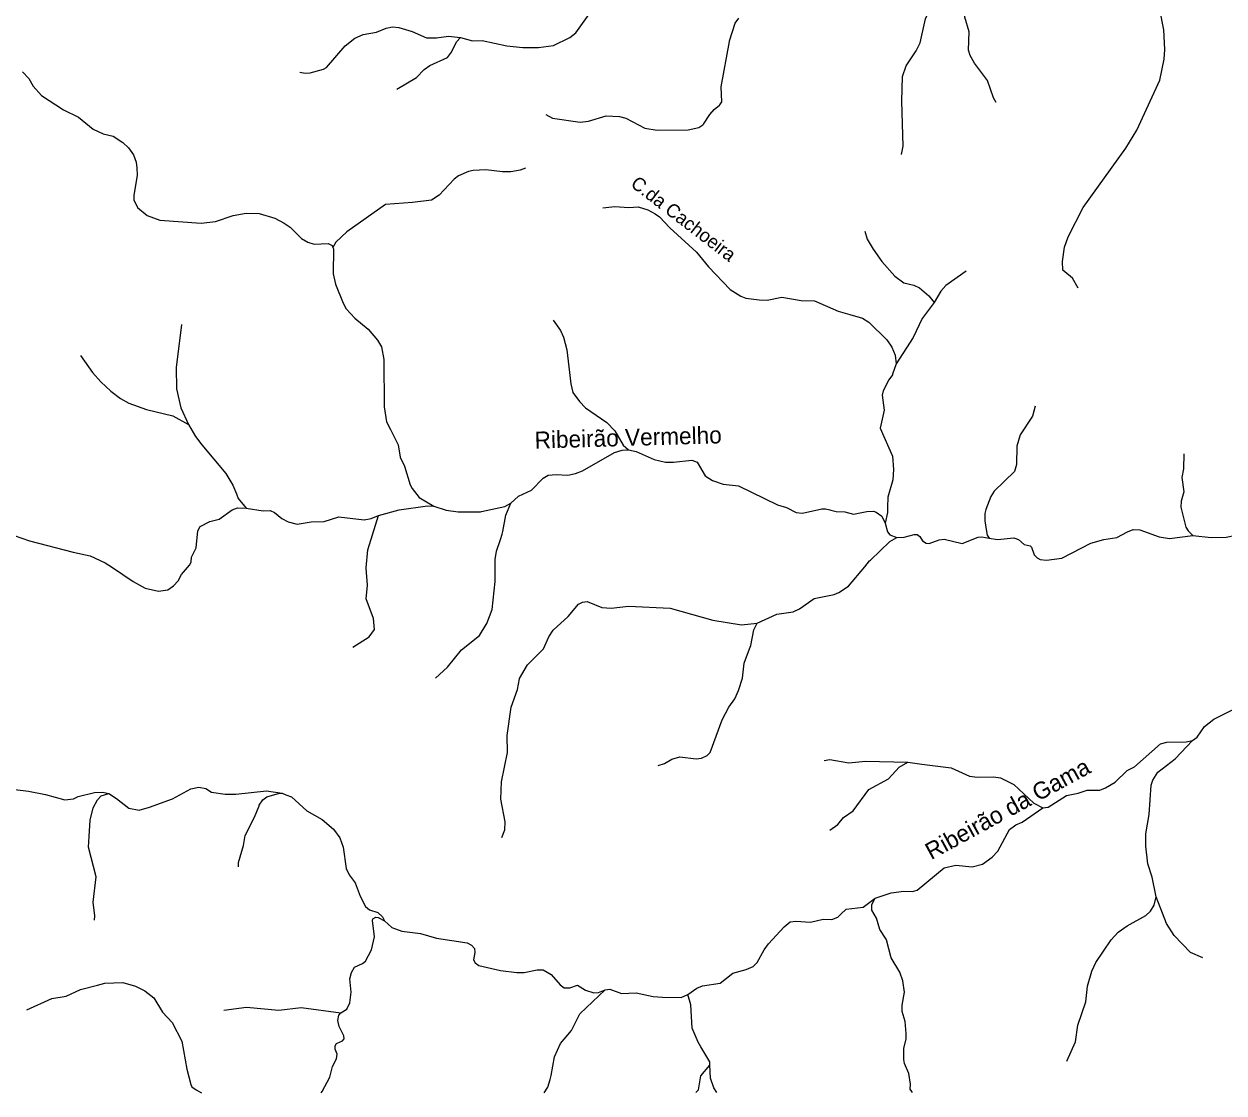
# Model space of a CAD drawing. Extents: x 473.9 to 500, y 7733.1 to 7760.8.
# Drawn here: x 487.45 to 494.55, y 7733.15 to 7739.47 of the extents above; entities that cross this region are included whole.
import ezdxf
from ezdxf.enums import TextEntityAlignment as Align

# ---------------------------------------------------------------- set-up
doc = ezdxf.new("R2010")
doc.units = 0
doc.header["$LTSCALE"] = 0.032
doc.layers.add('61', color=7, linetype='Continuous')
doc.layers.add('7', color=7, linetype='Continuous', lineweight=25)

msp = doc.modelspace()

# ---------------------------------------------------------------- linework, layer by layer
at = {"layer": '7'}
for points in [[(493.6912, 7737.9093), (493.6577, 7737.9688), (493.6116, 7738.0062), (493.6003, 7738.0154), (493.5974, 7738.0668), (493.61, 7738.1504), (493.6319, 7738.2133), (493.7196, 7738.3864), (493.9716, 7738.7369), (494.0376, 7738.8435), (494.0496, 7738.8696), (494.1733, 7739.1388), (494.2, 7739.2633), (494.2032, 7739.3203), (494.1976, 7739.4368), (494.1743, 7739.557), (494.1743, 7739.5915), (494.1743, 7739.6289), (494.2017, 7739.7973), (494.222, 7739.8595), (494.2343, 7739.8973), (494.2556, 7739.9383)], [(490.0364, 7739.3905), (490.1076, 7739.3721), (490.1641, 7739.3732), (490.3094, 7739.3429), (490.4052, 7739.3316), (490.4964, 7739.3316), (490.5852, 7739.3443), (490.6836, 7739.3919), (490.7178, 7739.4189), (490.8371, 7739.5847), (490.9115, 7739.6731), (490.9589, 7739.7258), (491.038, 7739.7976), (491.0653, 7739.8128), (491.084, 7739.815)], [(490.5407, 7738.9368), (490.5796, 7738.9151), (490.7432, 7738.8907), (490.7926, 7738.8955), (490.8972, 7738.9275), (490.9755, 7738.9242), (491.0139, 7738.9137), (491.1269, 7738.8556), (491.1986, 7738.8426), (491.3834, 7738.845), (491.4457, 7738.8589), (491.4689, 7738.8746), (491.4744, 7738.8783), (491.5119, 7738.936), (491.5369, 7738.9664), (491.5691, 7738.9915), (491.5702, 7738.9933), (491.5812, 7739.0106), (491.5782, 7739.0996), (491.6273, 7739.3685), (491.628, 7739.3723), (491.6613, 7739.4769), (491.683, 7739.5064)], [(492.6452, 7738.6987), (492.6541, 7738.7489), (492.6469, 7739.0153), (492.651, 7739.1606), (492.6735, 7739.2246), (492.7318, 7739.3132), (492.7545, 7739.3588), (492.7874, 7739.5024), (492.8039, 7739.5382)], [(493.2053, 7739.0062), (493.1897, 7739.0345), (493.154, 7739.1369), (493.0778, 7739.2391), (493.0515, 7739.2841), (493.0422, 7739.3172), (493.0462, 7739.4255), (493.0198, 7739.5121), (493.02, 7739.529), (493.037, 7739.5535)], [(489.086, 7739.1867), (489.1167, 7739.18), (489.1462, 7739.1825), (489.2253, 7739.2031), (489.2438, 7739.2142), (489.3537, 7739.3418), (489.4096, 7739.3866), (489.4597, 7739.4098), (489.5386, 7739.4222), (489.5956, 7739.4466), (489.6327, 7739.4542), (489.6701, 7739.451), (489.7494, 7739.4257), (489.8338, 7739.3889), (489.893, 7739.3894), (489.9643, 7739.3989), (490.0364, 7739.3905)], [(489.6591, 7739.0864), (489.7745, 7739.1544), (489.8204, 7739.2023), (489.8537, 7739.2259), (489.9582, 7739.2726), (489.9833, 7739.3036), (490.0116, 7739.3651), (490.0364, 7739.3905)], [(487.4447, 7739.1879), (487.482, 7739.1485), (487.5073, 7739.1041), (487.5573, 7739.0482), (487.6865, 7738.9634), (487.7754, 7738.9206), (487.8629, 7738.8483), (487.9214, 7738.8219), (487.98, 7738.8079), (488.0372, 7738.7697), (488.0706, 7738.7396), (488.1006, 7738.6968), (488.1161, 7738.6545), (488.1209, 7738.6209), (488.1217, 7738.5767), (488.1028, 7738.4565), (488.1038, 7738.4315), (488.1241, 7738.3865), (488.181, 7738.3392), (488.2567, 7738.3115), (488.5019, 7738.294), (488.5864, 7738.3035), (488.6908, 7738.3383), (488.7679, 7738.3533), (488.8447, 7738.3501), (488.9373, 7738.3228), (488.9929, 7738.2934), (489.027, 7738.2692), (489.0958, 7738.2034), (489.1321, 7738.1813), (489.1697, 7738.1694), (489.2526, 7738.1722), (489.2759, 7738.1603), (489.2809, 7738.1501)], [(490.4204, 7738.6182), (490.3878, 7738.606), (490.3332, 7738.5964), (490.2837, 7738.5964), (490.1854, 7738.6092), (490.1115, 7738.6052), (490.0822, 7738.598), (490.0248, 7738.5734), (489.9981, 7738.5534), (489.9096, 7738.4592), (489.8634, 7738.4299), (489.7521, 7738.4155), (489.5927, 7738.4046), (489.3634, 7738.2411), (489.2983, 7738.1815), (489.2809, 7738.1501)], [(490.8776, 7738.3837), (490.9495, 7738.3927), (491.031, 7738.3863), (491.0874, 7738.3894), (491.1438, 7738.3725), (491.1884, 7738.3486), (491.2128, 7738.3313), (491.2744, 7738.265), (491.4319, 7738.1212), (491.5037, 7738.0343), (491.6304, 7737.901), (491.6935, 7737.8611), (491.724, 7737.8495), (491.8035, 7737.8403), (491.8498, 7737.8387), (491.9363, 7737.8548), (492.0508, 7737.8363), (492.1294, 7737.8339), (492.2693, 7737.7719), (492.3388, 7737.7527), (492.4138, 7737.7319), (492.4518, 7737.7073), (492.5586, 7737.6035), (492.5869, 7737.5609), (492.6084, 7737.5131), (492.6138, 7737.461)], [(492.429, 7738.2467), (492.4427, 7738.1989), (492.4766, 7738.1401), (492.528, 7738.0666), (492.6056, 7737.9792), (492.6595, 7737.9409), (492.7189, 7737.9266), (492.7509, 7737.9099), (492.8063, 7737.8636), (492.838, 7737.824)], [(489.2809, 7738.1501), (489.2851, 7738.1416), (489.2827, 7737.9939), (489.2969, 7737.9335), (489.3405, 7737.8208), (489.36, 7737.7875), (489.4106, 7737.7306), (489.49, 7737.6665), (489.5437, 7737.6008), (489.568, 7737.5612), (489.5816, 7737.4865), (489.5833, 7737.2077), (489.5981, 7737.1175), (489.6209, 7737.0723), (489.6666, 7736.9819), (489.6796, 7736.9087), (489.7034, 7736.8572), (489.7374, 7736.7464), (489.7488, 7736.7236), (489.792, 7736.6702), (489.878, 7736.619)], [(493.0284, 7738.0102), (492.9072, 7737.9242), (492.8787, 7737.8921), (492.838, 7737.824)], [(492.838, 7737.824), (492.7681, 7737.7286), (492.7145, 7737.6163), (492.6138, 7737.461)], [(490.5843, 7737.7206), (490.6271, 7737.6577), (490.6452, 7737.6188), (490.664, 7737.5452), (490.6882, 7737.3425), (490.7006, 7737.2917), (490.7399, 7737.2381), (490.7753, 7737.2022), (490.9019, 7737.1142), (490.9495, 7737.0649), (490.9975, 7736.981), (491.0299, 7736.9527)], [(488.3856, 7737.6935), (488.3525, 7737.4406), (488.3557, 7737.3143), (488.3804, 7737.2011), (488.4272, 7737.1028)], [(487.7868, 7737.5099), (487.8583, 7737.4107), (487.9079, 7737.3549), (487.966, 7737.2998), (488.0231, 7737.2559), (488.0734, 7737.2283), (488.1775, 7737.1912), (488.3328, 7737.153), (488.4272, 7737.1028)], [(492.6138, 7737.461), (492.5924, 7737.4003), (492.5909, 7737.3961), (492.5693, 7737.3675), (492.5367, 7737.3018), (492.5314, 7737.2771), (492.5418, 7737.1873), (492.5195, 7737.0812), (492.5915, 7736.9146), (492.598, 7736.8367), (492.5931, 7736.7755), (492.5636, 7736.6732), (492.563, 7736.6146), (492.5627, 7736.583), (492.5477, 7736.5188)], [(493.4354, 7737.211), (493.4201, 7737.1514), (493.3466, 7737.0411), (493.3277, 7736.9746), (493.3259, 7736.8653), (493.3132, 7736.8255), (493.1934, 7736.7078), (493.1728, 7736.676), (493.1436, 7736.6007), (493.1371, 7736.5755), (493.1374, 7736.5328), (493.1459, 7736.4823), (493.1517, 7736.4476), (493.1633, 7736.4305)], [(488.4272, 7737.1028), (488.4673, 7737.0321), (488.5047, 7736.9826), (488.6478, 7736.8138), (488.6893, 7736.7434), (488.71, 7736.6927), (488.7212, 7736.6651), (488.7677, 7736.6081)], [(490.3337, 7736.6383), (490.3789, 7736.6794), (490.4567, 7736.7147), (490.5243, 7736.7849), (490.5544, 7736.8024), (490.6016, 7736.8068), (490.6713, 7736.8036), (490.7159, 7736.8122), (490.7569, 7736.828), (490.946, 7736.9365), (490.9913, 7736.951), (491.0299, 7736.9527)], [(491.0299, 7736.9527), (491.0757, 7736.9429), (491.1817, 7736.8956), (491.249, 7736.8806), (491.2967, 7736.88), (491.4036, 7736.8917), (491.4368, 7736.8804), (491.4839, 7736.7993), (491.5269, 7736.7706), (491.5906, 7736.7491), (491.681, 7736.7401), (491.9104, 7736.6285), (491.9648, 7736.6118), (492.0219, 7736.5819), (492.0591, 7736.5775), (492.174, 7736.6048), (492.1961, 7736.6046), (492.2203, 7736.5982), (492.2261, 7736.5967), (492.2593, 7736.5879), (492.3104, 7736.5855), (492.3615, 7736.5727), (492.4399, 7736.5887), (492.4784, 7736.5893), (492.4959, 7736.5847), (492.5292, 7736.5602), (492.5477, 7736.5188)], [(494.3156, 7736.9284), (494.3137, 7736.8396), (494.3034, 7736.7902), (494.3153, 7736.7049), (494.3002, 7736.6492), (494.2986, 7736.6147), (494.3276, 7736.4961), (494.3404, 7736.4729), (494.3693, 7736.4469)], [(494.3693, 7736.4469), (494.4776, 7736.4345), (494.5663, 7736.4364), (494.624, 7736.4477), (494.6818, 7736.4679), (494.8194, 7736.5348), (494.9304, 7736.5667), (495.0001, 7736.6063), (495.0443, 7736.6159), (495.1929, 7736.6208), (495.2361, 7736.6345), (495.2605, 7736.6501), (495.333, 7736.7221), (495.3612, 7736.7327), (495.4214, 7736.7375)], [(487.3957, 7736.4468), (487.4861, 7736.4154), (487.7437, 7736.3474), (487.8453, 7736.3264), (487.9342, 7736.2852), (487.9773, 7736.2562), (488.0995, 7736.174), (488.1708, 7736.1339), (488.2488, 7736.1165), (488.3046, 7736.1258), (488.3373, 7736.1482), (488.3649, 7736.1783), (488.3842, 7736.2162), (488.432, 7736.2709), (488.4415, 7736.2891), (488.445, 7736.3175), (488.4721, 7736.3737), (488.4814, 7736.4729), (488.4957, 7736.5001), (488.5516, 7736.5291), (488.6086, 7736.5423), (488.6855, 7736.5984), (488.717, 7736.6102), (488.7677, 7736.6081)], [(488.7677, 7736.6081), (488.8675, 7736.5916), (488.9091, 7736.5942), (488.9348, 7736.5826), (488.9782, 7736.5477), (489.016, 7736.5267), (489.0696, 7736.5125), (489.1523, 7736.527), (489.2294, 7736.5299), (489.3167, 7736.5574), (489.4657, 7736.5383), (489.5073, 7736.5468), (489.5506, 7736.5645)], [(489.5506, 7736.5645), (489.6727, 7736.5975), (489.8414, 7736.6215), (489.878, 7736.619)], [(489.878, 7736.619), (489.9502, 7736.5952), (490.0223, 7736.5856), (490.1532, 7736.5871), (490.1594, 7736.5884), (490.2978, 7736.6173), (490.3337, 7736.6383)], [(489.8871, 7735.6022), (489.9591, 7735.668), (490.0417, 7735.7706), (490.1491, 7735.8556), (490.1881, 7735.9198), (490.1906, 7735.9263), (490.2223, 7736.0091), (490.2399, 7736.1735), (490.2408, 7736.3034), (490.2492, 7736.3533), (490.272, 7736.4229), (490.2825, 7736.4551), (490.2854, 7736.4709), (490.3032, 7736.5667), (490.3337, 7736.6383)], [(489.3989, 7735.7865), (489.4953, 7735.8473), (489.5266, 7735.8903), (489.52, 7735.9557), (489.4767, 7736.0709), (489.4847, 7736.1518), (489.4769, 7736.2523), (489.4767, 7736.2555), (489.4871, 7736.362), (489.4968, 7736.3929), (489.5506, 7736.5645)], [(492.5477, 7736.5188), (492.5613, 7736.4685), (492.5759, 7736.4507), (492.6181, 7736.4342)], [(491.7908, 7735.9276), (491.9071, 7735.9818), (492.0041, 7735.9949), (492.0409, 7736.0134), (492.1292, 7736.074), (492.2459, 7736.0974), (492.2734, 7736.1089), (492.3315, 7736.1467), (492.4275, 7736.2618), (492.4561, 7736.2961), (492.4609, 7736.3007), (492.5763, 7736.4105), (492.6181, 7736.4342)], [(492.6181, 7736.4342), (492.6615, 7736.4357), (492.7207, 7736.453), (492.7376, 7736.4524), (492.7541, 7736.4413), (492.7692, 7736.415), (492.7908, 7736.4011), (492.808, 7736.3995), (492.8676, 7736.4204), (492.8969, 7736.4243), (493.0047, 7736.3995), (493.0987, 7736.4364), (493.12, 7736.4387), (493.1633, 7736.4305)], [(493.1633, 7736.4305), (493.2134, 7736.422), (493.3089, 7736.4331), (493.3372, 7736.4218), (493.3715, 7736.3937), (493.4065, 7736.3845), (493.4141, 7736.3775), (493.4309, 7736.3316), (493.4474, 7736.3139), (493.4652, 7736.3047), (493.5033, 7736.3), (493.5945, 7736.3131), (493.765, 7736.4009), (493.8423, 7736.4219), (493.92, 7736.4342), (493.9821, 7736.4689), (494.0164, 7736.4811), (494.0556, 7736.4804), (494.1703, 7736.4389), (494.2308, 7736.4283), (494.3693, 7736.4469)], [(490.2807, 7734.6598), (490.2975, 7734.7048), (490.3, 7734.7521), (490.2753, 7734.8875), (490.2788, 7734.9903), (490.313, 7735.1627), (490.3114, 7735.2639), (490.3362, 7735.432), (490.3736, 7735.5353), (490.3848, 7735.5979), (490.3854, 7735.6011), (490.4329, 7735.6816), (490.5263, 7735.7759), (490.5584, 7735.8473), (490.5845, 7735.8869), (490.6718, 7735.9678), (490.7341, 7736.0404), (490.7572, 7736.0519), (490.7854, 7736.0556), (490.8722, 7736.0203), (490.928, 7736.0171), (491.0292, 7736.0283), (491.2753, 7736.017), (491.5284, 7735.9461), (491.6993, 7735.9177), (491.7908, 7735.9276)], [(494.3667, 7735.2345), (494.3953, 7735.2545), (494.4371, 7735.316), (494.4923, 7735.3607), (494.6351, 7735.432), (494.7838, 7735.4917), (494.8044, 7735.5195), (494.8036, 7735.5797), (494.8396, 7735.6239), (494.8511, 7735.6825), (494.8717, 7735.7284), (494.8952, 7735.7581), (494.9656, 7735.8038), (495.0234, 7735.8606), (495.0541, 7735.8763), (495.2048, 7735.9228), (495.2996, 7735.9689), (495.4546, 7735.9674), (495.54, 7735.997)], [(491.2056, 7735.0856), (491.242, 7735.0971), (491.2868, 7735.1233), (491.334, 7735.1374), (491.4299, 7735.1263), (491.462, 7735.1293), (491.4944, 7735.1445), (491.513, 7735.1633), (491.5844, 7735.356), (491.6237, 7735.4314), (491.6586, 7735.4812), (491.6805, 7735.5305), (491.7039, 7735.6033), (491.7143, 7735.6909), (491.7455, 7735.7756), (491.7527, 7735.7951), (491.7706, 7735.8876), (491.7908, 7735.9276)], [(493.4805, 7734.8352), (493.5134, 7734.8393), (493.6207, 7734.9096), (493.6894, 7734.9227), (493.7442, 7734.941), (493.8192, 7734.941), (493.8286, 7734.9445), (493.8529, 7734.9535), (493.91, 7734.9886), (493.9797, 7735.0566), (494.0245, 7735.0785), (494.1771, 7735.215), (494.2156, 7735.2232), (494.3302, 7735.2265), (494.3667, 7735.2345)], [(494.152, 7734.3093), (494.1278, 7734.4259), (494.1024, 7734.5051), (494.0908, 7734.6092), (494.0908, 7734.6387), (494.0909, 7734.6812), (494.1109, 7734.7964), (494.1222, 7734.9703), (494.1324, 7735), (494.1612, 7735.0459), (494.2635, 7735.1255), (494.3667, 7735.2345)], [(492.1876, 7735.1165), (492.2201, 7735.1222), (492.3325, 7735.1029), (492.4317, 7735.1119), (492.6822, 7735.1059)], [(492.2218, 7734.7041), (492.2682, 7734.7371), (492.3018, 7734.7782), (492.3597, 7734.8175), (492.451, 7734.944), (492.568, 7735.0064), (492.6311, 7735.0769), (492.6822, 7735.1059)], [(492.6822, 7735.1059), (492.766, 7735.095), (492.9392, 7735.0726), (493.048, 7735.0226), (493.0947, 7735.0173), (493.1901, 7735.0196), (493.231, 7735.0132), (493.3089, 7734.9743), (493.4289, 7734.8638), (493.4805, 7734.8352)], [(486.9507, 7734.8002), (487.0009, 7734.8109), (487.0403, 7734.8265), (487.1798, 7734.9042), (487.287, 7734.9346), (487.3547, 7734.9443), (487.374, 7734.9446), (487.3989, 7734.9451), (487.4798, 7734.9346), (487.5801, 7734.9154), (487.6953, 7734.8833), (487.7453, 7734.8897), (487.7738, 7734.9031), (487.87, 7734.9273), (487.9191, 7734.9282), (487.9548, 7734.9203)], [(487.9548, 7734.9203), (488.0008, 7734.8919), (488.073, 7734.8334), (488.1345, 7734.8223), (488.1965, 7734.8394), (488.3312, 7734.8899), (488.4396, 7734.9489), (488.4877, 7734.9586), (488.5297, 7734.9498), (488.5625, 7734.9289), (488.6431, 7734.9168), (488.7068, 7734.917), (488.8884, 7734.9363), (488.9802, 7734.922)], [(487.8698, 7734.1713), (487.873, 7734.1972), (487.8627, 7734.2777), (487.8805, 7734.428), (487.8338, 7734.6023), (487.8384, 7734.6673), (487.8451, 7734.763), (487.8625, 7734.8349), (487.8885, 7734.8836), (487.9097, 7734.9071), (487.9548, 7734.9203)], [(488.7222, 7734.4864), (488.7222, 7734.5135), (488.7519, 7734.6126), (488.7615, 7734.6721), (488.817, 7734.7812), (488.8436, 7734.848), (488.8452, 7734.8519), (488.8661, 7734.8838), (488.8906, 7734.9017), (488.9654, 7734.923), (488.9802, 7734.922)], [(488.9802, 7734.922), (489.0017, 7734.9137), (489.0362, 7734.9003), (489.1265, 7734.8179), (489.2174, 7734.7659), (489.2846, 7734.7106), (489.3226, 7734.6575), (489.3412, 7734.6023), (489.3591, 7734.4766), (489.3766, 7734.4388), (489.4122, 7734.3924), (489.4412, 7734.3127), (489.4729, 7734.2532), (489.4973, 7734.2331), (489.5465, 7734.2176), (489.5748, 7734.191), (489.5863, 7734.1683)], [(492.49, 7734.3023), (492.5832, 7734.334), (492.6593, 7734.3429), (492.7106, 7734.3412), (492.7386, 7734.3491), (492.8979, 7734.4804), (492.966, 7734.4961), (493.0634, 7734.4865), (493.1252, 7734.5034), (493.1816, 7734.545), (493.2147, 7734.5805), (493.2848, 7734.7082), (493.3212, 7734.7349), (493.3583, 7734.7512), (493.4805, 7734.8352)], [(491.3813, 7733.7314), (491.4341, 7733.769), (491.4678, 7733.7836), (491.5729, 7733.7981), (491.6464, 7733.8575), (491.7267, 7733.8798), (491.7668, 7733.8975), (491.7915, 7733.9222), (491.8324, 7733.9968), (491.8589, 7734.0313), (491.9499, 7734.1326), (491.9857, 7734.1608), (492.0197, 7734.1658), (492.1068, 7734.1593), (492.181, 7734.1777), (492.2325, 7734.1746), (492.2682, 7734.1898), (492.2864, 7734.2069), (492.318, 7734.2365), (492.419, 7734.2493), (492.49, 7734.3023)], [(492.7103, 7733.1528), (492.7062, 7733.1587), (492.6963, 7733.1727), (492.6989, 7733.2015), (492.6893, 7733.265), (492.6624, 7733.324), (492.659, 7733.3468), (492.6596, 7733.4133), (492.6724, 7733.4698), (492.6734, 7733.5005), (492.666, 7733.5722), (492.6493, 7733.6306), (492.6493, 7733.6694), (492.6621, 7733.7457), (492.6533, 7733.8137), (492.6344, 7733.8644), (492.5846, 7733.9479), (492.5555, 7734.0555), (492.5545, 7734.0593), (492.5167, 7734.1157), (492.4972, 7734.1835), (492.4697, 7734.2311), (492.4696, 7734.264), (492.49, 7734.3023)], [(493.6223, 7733.3373), (493.6743, 7733.453), (493.6886, 7733.5516), (493.7348, 7733.688), (493.7454, 7733.7819), (493.7713, 7733.8708), (493.7941, 7733.9209), (493.8847, 7734.0544), (493.9273, 7734.0998), (493.9805, 7734.1381), (494.0914, 7734.1985), (494.1184, 7734.2248), (494.1405, 7734.2608), (494.152, 7734.3093)], [(494.4277, 7733.9485), (494.3554, 7733.9798), (494.2574, 7734.0818), (494.213, 7734.1515), (494.152, 7734.3093)], [(489.3281, 7733.6234), (489.3637, 7733.6448), (489.3801, 7733.6826), (489.3884, 7733.7467), (489.3813, 7733.8253), (489.3906, 7733.8627), (489.4087, 7733.8932), (489.4565, 7733.9147), (489.473, 7733.9301), (489.5094, 7733.9962), (489.5263, 7734.0723), (489.5144, 7734.1694), (489.5178, 7734.1787), (489.5348, 7734.1887), (489.5477, 7734.1881), (489.5863, 7734.1683)], [(489.5863, 7734.1683), (489.63, 7734.1284), (489.6304, 7734.1282), (489.688, 7734.1059), (489.7989, 7734.0935), (489.8943, 7734.0646), (490.0755, 7734.0382), (490.1015, 7734.0243), (490.1186, 7734.0031), (490.1204, 7733.9809), (490.1125, 7733.9376), (490.1224, 7733.9187), (490.1448, 7733.9042), (490.2725, 7733.8731), (490.3698, 7733.8621), (490.412, 7733.8626), (490.4886, 7733.8778), (490.5242, 7733.877), (490.5729, 7733.8512), (490.6258, 7733.7886), (490.6482, 7733.7706), (490.6821, 7733.7709), (490.7279, 7733.7864), (490.775, 7733.7567), (490.8241, 7733.7417), (490.8514, 7733.7447), (490.8909, 7733.7596)], [(487.4696, 7733.642), (487.6183, 7733.7092), (487.7026, 7733.7216), (487.7867, 7733.7606), (487.8875, 7733.7875), (487.9316, 7733.7992), (488.0377, 7733.8025), (488.1122, 7733.7812), (488.1679, 7733.7532), (488.2208, 7733.7129), (488.2722, 7733.6268), (488.3296, 7733.5669), (488.3861, 7733.4559), (488.4159, 7733.2898), (488.4405, 7733.2007), (488.447, 7733.1865), (488.4715, 7733.1689), (488.5031, 7733.1496)], [(490.5314, 7733.1512), (490.5521, 7733.1841), (490.567, 7733.2284), (490.5715, 7733.2535), (490.591, 7733.3626), (490.6281, 7733.4422), (490.6918, 7733.5198), (490.7411, 7733.6171), (490.8909, 7733.7596)], [(490.8909, 7733.7596), (490.9196, 7733.7642), (490.989, 7733.7384), (491.0746, 7733.7415), (491.1753, 7733.7208), (491.231, 7733.7168), (491.341, 7733.7144), (491.3813, 7733.7314)], [(491.5114, 7733.3139), (491.5105, 7733.3332), (491.4583, 7733.4219), (491.442, 7733.4495), (491.4065, 7733.5335), (491.3978, 7733.6707), (491.3813, 7733.7314)], [(488.6353, 7733.6401), (488.7702, 7733.6573), (488.9606, 7733.6389), (489.0926, 7733.6549), (489.3281, 7733.6234)], [(489.2122, 7733.1502), (489.2168, 7733.1585), (489.2632, 7733.2425), (489.2784, 7733.3063), (489.3028, 7733.3517), (489.3058, 7733.3788), (489.2942, 7733.4082), (489.2935, 7733.428), (489.3027, 7733.4424), (489.338, 7733.4573), (489.3474, 7733.4706), (489.3451, 7733.4883), (489.3175, 7733.5423), (489.3092, 7733.5784), (489.3156, 7733.61), (489.3281, 7733.6234)], [(491.4273, 7733.1519), (491.4328, 7733.1573), (491.4442, 7733.1685), (491.4583, 7733.2519), (491.5114, 7733.3139)], [(491.5521, 7733.152), (491.535, 7733.1791), (491.5147, 7733.238), (491.5114, 7733.3139)]]:
    msp.add_lwpolyline(points, dxfattribs=at)

# ---------------------------------------------------------------- texts
at = {"layer": '61'}
for s, height, rotation, p in [('C.da Cachoeira', 0.08, 322.431, (491.3313, 7738.2881)), ('Ribeirão Vermelho', 0.1, 1.645, (491.0291, 7736.976)), ('Ribeirão da Gama', 0.1, 28.692, (493.2966, 7734.7864))]:
    msp.add_text(s, height=height, rotation=rotation, dxfattribs=at).set_placement(p, align=Align.CENTER)

doc.saveas('drawing.dxf')
